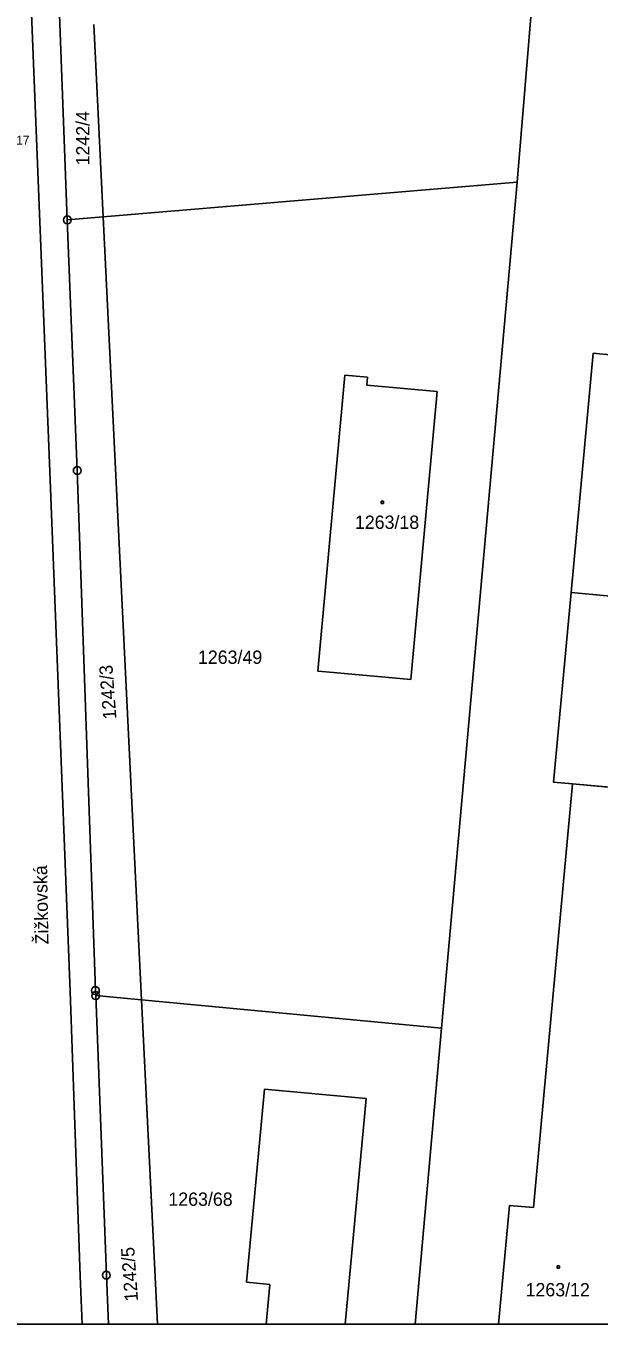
# Model space of a CAD drawing. Extents: x -468021 to -466942, y -1130484 to -1128584.
# Drawn here: x -467574.3 to -467501, y -1130484.4 to -1130318.6 of the extents above; entities that cross this region are included whole.
import ezdxf

# ---------------------------------------------------------------- set-up
doc = ezdxf.new("R2010")
doc.units = 0
for name, color, linetype in [('22-Odběrná místa-šrafy', 7, 'Continuous'), ('Default', 7, 'Continuous'), ('DKM', 7, 'Continuous')]:
    doc.layers.add(name, color=color, linetype=linetype)

msp = doc.modelspace()

# ---------------------------------------------------------------- linework, layer by layer
at = {"layer": '22-Odběrná místa-šrafy'}
for points in [[(-467499.17, -1130360.66), (-467501.73, -1130360.43), (-467504.57, -1130390.98)], [(-467504.57, -1130390.98), (-467371.12, -1130403.34), (-467368.24, -1130372.8), (-467371.68, -1130372.48), (-467375.66, -1130372.12), (-467378.16, -1130371.89)], [(-467371.12, -1130403.34), (-467504.57, -1130390.98), (-467506.83, -1130415.18), (-467504.4, -1130415.41), (-467493.89, -1130416.38), (-467382.28, -1130426.72), (-467373.43, -1130427.45), (-467371.12, -1130403.34)]]:
    msp.add_lwpolyline(points, dxfattribs=at)
at = {"layer": 'Default'}
msp.add_lwpolyline([(-468020.6, -1128583.91), (-466941.68, -1128583.91), (-466941.68, -1130484.41), (-468020.6, -1130484.41)], close=True, dxfattribs=at)
at = {"layer": 'DKM'}
for p, q in [((-467504.49, -1130254.71), (-467511.48, -1130338.57)), ((-467571.21, -1130375.53), (-467574.05, -1130305.29)), ((-467568.98, -1130343.39), (-467570.44, -1130305.16)), ((-467565.58, -1130318.42), (-467564.38, -1130343)), ((-467511.48, -1130338.57), (-467564.38, -1130343)), ((-467521.12, -1130446.64), (-467511.48, -1130338.57)), ((-467564.38, -1130343), (-467568.98, -1130343.39)), ((-467559.5, -1130443.01), (-467564.38, -1130343)), ((-467568.98, -1130343.39), (-467567.71, -1130375.4)), ((-467501.73, -1130360.43), (-467504.57, -1130390.98)), ((-467499.17, -1130360.66), (-467501.73, -1130360.43)), ((-467536.94, -1130401.01), (-467533.49, -1130363.22)), ((-467533.49, -1130363.22), (-467530.6, -1130363.49)), ((-467530.6, -1130363.49), (-467530.69, -1130364.48)), ((-467530.69, -1130364.48), (-467521.68, -1130365.31)), ((-467521.68, -1130365.31), (-467525.06, -1130402.1)), ((-467568.63, -1130441.94), (-467571.21, -1130375.53)), ((-467567.71, -1130375.4), (-467565.39, -1130441.82)), ((-467528.87, -1130379.33), (-467528.57, -1130379.33)), ((-467528.87, -1130379.63), (-467528.87, -1130379.33)), ((-467528.57, -1130379.63), (-467528.87, -1130379.63)), ((-467528.57, -1130379.33), (-467528.57, -1130379.63)), ((-467504.57, -1130390.98), (-467506.83, -1130415.18)), ((-467371.12, -1130403.34), (-467504.57, -1130390.98)), ((-467534.95, -1130401.19), (-467536.94, -1130401.01)), ((-467525.06, -1130402.1), (-467534.95, -1130401.19)), ((-467509.38, -1130469.54), (-467504.4, -1130415.41)), ((-467506.83, -1130415.18), (-467504.4, -1130415.41)), ((-467504.4, -1130415.41), (-467493.89, -1130416.38)), ((-467567.34, -1130478.29), (-467568.63, -1130441.94)), ((-467565.39, -1130441.82), (-467565.35, -1130442.46)), ((-467565.35, -1130442.46), (-467563.99, -1130478.17)), ((-467565.35, -1130442.46), (-467559.5, -1130443.01)), ((-467559.5, -1130443.01), (-467557.47, -1130484.41)), ((-467559.5, -1130443.01), (-467521.12, -1130446.64)), ((-467524.49, -1130484.41), (-467521.12, -1130446.64)), ((-467546.06, -1130479.06), (-467543.79, -1130454.42)), ((-467543.79, -1130454.42), (-467530.78, -1130455.62)), ((-467530.78, -1130455.62), (-467533.44, -1130484.41)), ((-467513.85, -1130484.41), (-467512.44, -1130469.26)), ((-467512.44, -1130469.26), (-467509.38, -1130469.54)), ((-467506.35, -1130476.96), (-467506.05, -1130476.96)), ((-467506.35, -1130477.26), (-467506.35, -1130476.96)), ((-467506.05, -1130477.26), (-467506.35, -1130477.26)), ((-467506.05, -1130476.96), (-467506.05, -1130477.26)), ((-467567.08, -1130484.41), (-467567.34, -1130478.29)), ((-467563.99, -1130478.17), (-467563.71, -1130484.41)), ((-467543.07, -1130479.34), (-467546.06, -1130479.06)), ((-467543.54, -1130484.41), (-467543.07, -1130479.34))]:
    msp.add_line(p, q, dxfattribs=at)
for centre, radius in [((-467568.98, -1130343.39), 0.5), ((-467568.98, -1130343.39), 0.01), ((-467567.71, -1130375.4), 0.5), ((-467567.71, -1130375.4), 0.01), ((-467565.39, -1130441.82), 0.5), ((-467565.35, -1130442.46), 0.5), ((-467565.39, -1130441.82), 0.01), ((-467565.35, -1130442.46), 0.01), ((-467563.99, -1130478.17), 0.5), ((-467563.99, -1130478.17), 0.01)]:
    msp.add_circle(centre, radius, dxfattribs=at)

# ---------------------------------------------------------------- texts
for s, rotation, p in [('1242/4', 90, (-467566.15, -1130336.44)), ('1242/3', 94.4148, (-467562.69, -1130407.11)), ('Žižkovská', 91.0939, (-467571.38, -1130435.91)), ('1242/5', 94.1665, (-467559.93, -1130481.46))]:
    msp.add_text(s, height=1.7, rotation=rotation, dxfattribs=at).set_placement(p)
for s, height, p in [('4349/17', 1.14, (-467579.33, -1130333.77)), ('1263/18', 1.7, (-467532.21, -1130382.85)), ('1263/49', 1.7, (-467552.28, -1130400.09)), ('1263/68', 1.7, (-467556.06, -1130469.31)), ('1263/12', 1.7, (-467510.39, -1130480.87))]:
    msp.add_text(s, height=height, dxfattribs=at).set_placement(p)

doc.saveas('drawing.dxf')
